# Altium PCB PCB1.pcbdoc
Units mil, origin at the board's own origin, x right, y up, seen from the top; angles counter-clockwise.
Board outline 2593.1 x 4516.05 mil, 2 copper layers (Top Layer, Bottom Layer); 41 components, 22 nets, 155 pads, 15 vias.
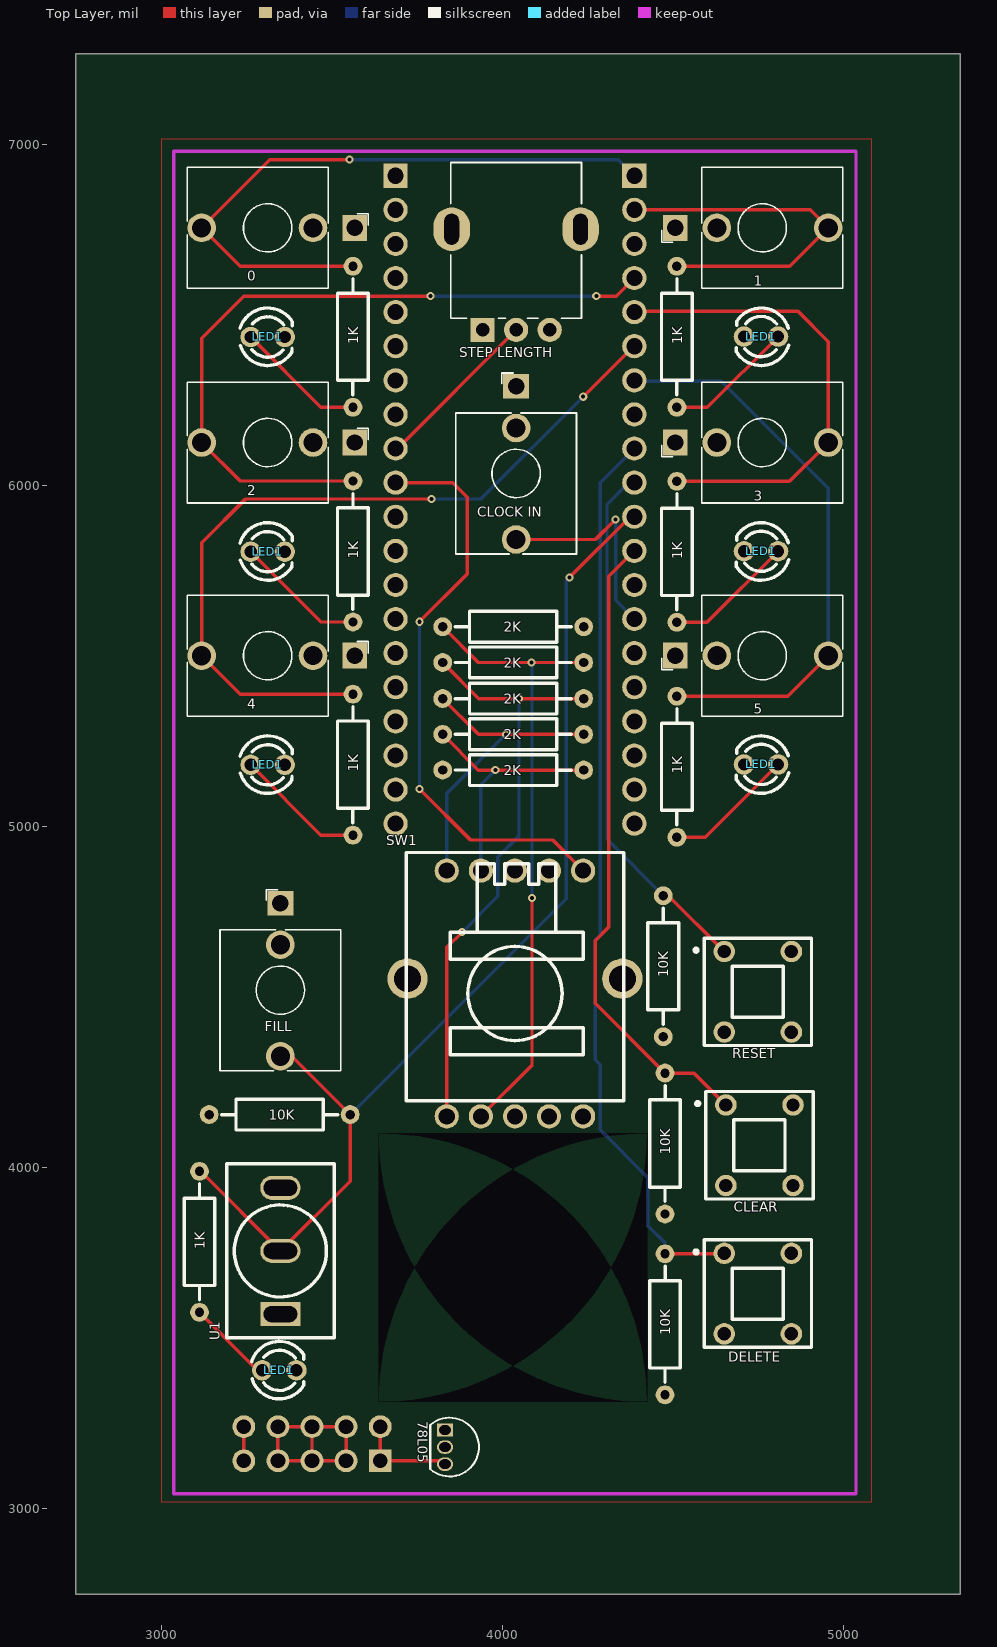
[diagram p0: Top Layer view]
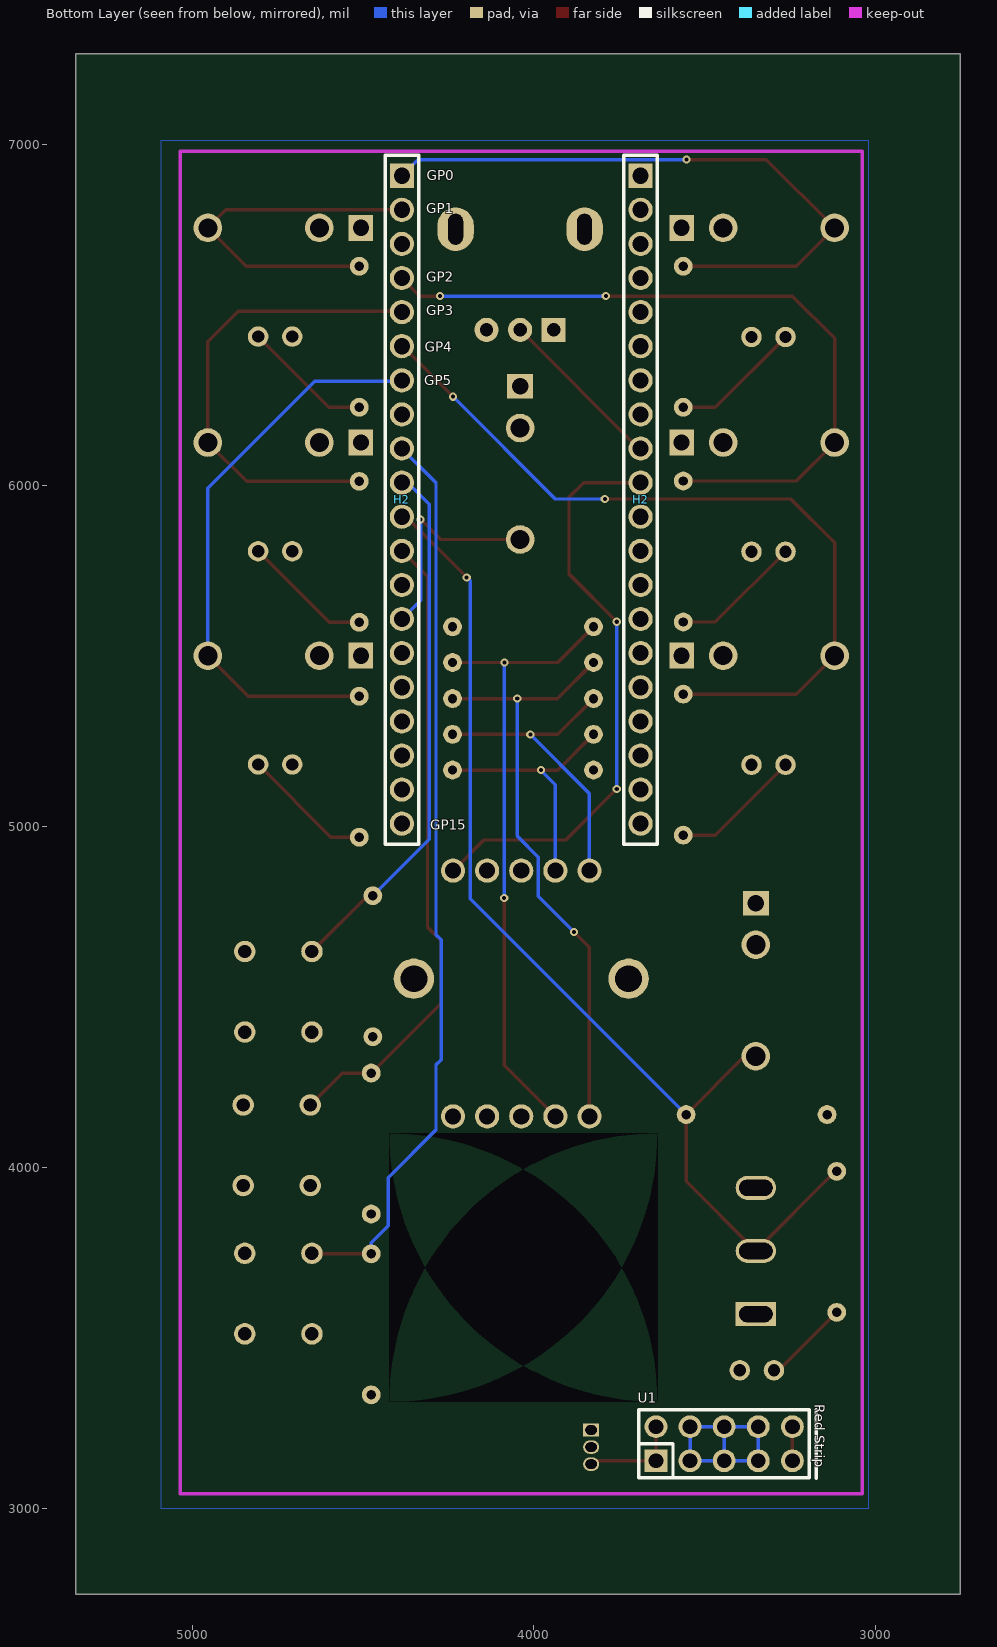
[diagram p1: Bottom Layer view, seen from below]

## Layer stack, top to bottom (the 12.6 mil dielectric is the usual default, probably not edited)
Top Layer: signal copper (thickness not stored)
Dielectric: dielectric 12.6, FR-4, Dk 4.8
Bottom Layer: signal copper (thickness not stored)

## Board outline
5343.1,2750 2750,2750 2750,7266.05 5343.1,7266.05
cut-out: 4424.72,4101.05 3637.32,4101.05 cw(c3637.32,3313.65) 4424.72,3313.65 4424.72,4101.05 cw(c3637.32,4101.05) 3637.32,3313.65 4424.72,3313.65 cw(c4424.72,4101.05) 3637.32,4101.05 3637.32,3313.65 cw(c4424.72,3313.65)

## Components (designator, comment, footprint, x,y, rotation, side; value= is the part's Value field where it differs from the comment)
0 "Connector_AudioJack2_SwitchT" benjiaomodular:AudioJack_3.5mm 3567.32,6756.05 r270 top
1 "Connector_AudioJack2_SwitchT" benjiaomodular:AudioJack_3.5mm 4507.31,6756.05 r90 top
1K "MF1/4W-1KΩ±1%T52" RES-TH_BD2.3-L6.5-P10.50-D0.5 3562.32,6436.64 r90 top
1K "MF1/4W-1KΩ±1%T52" RES-TH_BD2.3-L6.5-P10.50-D0.5 4512.31,6436.64 r90 top
1K "MF1/4W-1KΩ±1%T52" RES-TH_BD2.3-L6.5-P10.50-D0.5 3562.32,5807.13 r90 top
1K "MF1/4W-1KΩ±1%T52" RES-TH_BD2.3-L6.5-P10.50-D0.5 4512.31,5806.05 r90 top
1K "MF1/4W-1KΩ±1%T52" RES-TH_BD2.3-L6.5-P10.50-D0.5 3562.32,5182.13 r90 top
1K "MF1/4W-1KΩ±1%T52" RES-TH_BD2.3-L6.5-P10.50-D0.5 4512.31,5176.05 r90 top
1K "MF1/4W-1KΩ±1%T52" RES-TH_BD2.3-L6.5-P10.50-D0.5 3112.32,3782.71 r90 top
2 "Connector_AudioJack2_SwitchT" benjiaomodular:AudioJack_3.5mm 3567.32,6126.54 r270 top
2K "MF1/4W-1KΩ±1%T52" RES-TH_BD2.3-L6.5-P10.50-D0.5 4032.1,5375.84 r0 top
2K "MF1/4W-1KΩ±1%T52" RES-TH_BD2.3-L6.5-P10.50-D0.5 4032.1,5270.84 r0 top
2K "MF1/4W-1KΩ±1%T52" RES-TH_BD2.3-L6.5-P10.50-D0.5 4032.1,5166.26 r0 top
2K "MF1/4W-1KΩ±1%T52" RES-TH_BD2.3-L6.5-P10.50-D0.5 4032.1,5481.66 r0 top
2K "MF1/4W-1KΩ±1%T52" RES-TH_BD2.3-L6.5-P10.50-D0.5 4032.1,5586.23 r0 top
3 "Connector_AudioJack2_SwitchT" benjiaomodular:AudioJack_3.5mm 4507.31,6126.54 r90 top
4 "Connector_AudioJack2_SwitchT" benjiaomodular:AudioJack_3.5mm 3567.32,5501.54 r270 top
5 "Connector_AudioJack2_SwitchT" benjiaomodular:AudioJack_3.5mm 4507.31,5501.54 r90 top
10K "MF1/4W-1KΩ±1%T52" RES-TH_BD2.3-L6.5-P10.50-D0.5 3347.32,4156.05 r0 top
10K "MF1/4W-1KΩ±1%T52" RES-TH_BD2.3-L6.5-P10.50-D0.5 4472.31,4591.05 r90 top
10K "MF1/4W-1KΩ±1%T52" RES-TH_BD2.3-L6.5-P10.50-D0.5 4477.31,4071.05 r90 top
10K "MF1/4W-1KΩ±1%T52" RES-TH_BD2.3-L6.5-P10.50-D0.5 4477.31,3540.8 r90 top
78L05 "BC558" TO-92-3_L4.5-W3.5-P1.27-L 3832.32,3181.05 r270 top
CLEAR "BTSA-N-P-17" SW-TH_BTSA-X-P-17 4754.27,4066.05 r0 top
"CLOCK IN" "Connector_AudioJack2_SwitchT" benjiaomodular:AudioJack_3.5mm 4040.74,6291.05 r0 top
DELETE "BTSA-N-P-17" SW-TH_BTSA-X-P-17 4749.47,3631.05 r0 top
FILL "Connector_AudioJack2_SwitchT" benjiaomodular:AudioJack_3.5mm 3349.56,4776.05 r0 top
H2 "22850120ANG1SYA01" HDR-TH_20P-P2.54-V-F 4387.31,5958.97 r270 bottom
H2 "22850120ANG1SYA01" HDR-TH_20P-P2.54-V-F 3687.31,5958.97 r270 bottom
LED1 "204-10SURD/S530-A3-L" LED-TH_BD3.0-P2.54-FD 3312.32,6436.05 r0 top
LED1 "204-10SURD/S530-A3-L" LED-TH_BD3.0-P2.54-FD 4758.8,6437.23 r180 top
LED1 "204-10SURD/S530-A3-L" LED-TH_BD3.0-P2.54-FD 4758.8,5807.72 r180 top
LED1 "204-10SURD/S530-A3-L" LED-TH_BD3.0-P2.54-FD 3312.32,5806.54 r0 top
LED1 "204-10SURD/S530-A3-L" LED-TH_BD3.0-P2.54-FD 4758.8,5182.72 r180 top
LED1 "204-10SURD/S530-A3-L" LED-TH_BD3.0-P2.54-FD 3312.32,5181.54 r0 top
LED1 "204-10SURD/S530-A3-L" LED-TH_BD3.0-P2.54-FD 3346.43,3406.05 r0 top
RESET "BTSA-N-P-17" SW-TH_BTSA-X-P-17 4749.47,4516.05 r0 top
"STEP LENGTH" "BusinessCardOscillator-rescue_R_POT-Device" benjiaomodular:Potentiometer_RV09 3942.32,6456.84 r90 top
SW1 "SRBV151102" SW-TH_SRBV151102 4037.32,4511.05 r0 top
U1 "MT-0-102-A101-M200-RS" SW-TH_MT-0-103-A101-M200-RS 3349.56,3756.05 r90 top
U1 "ZX-PZ2.54-2-5PZZ" HDR-TH_10P-P2.54-V-M-R2-C5-S2.54 3442.32,3190.83 r180 bottom

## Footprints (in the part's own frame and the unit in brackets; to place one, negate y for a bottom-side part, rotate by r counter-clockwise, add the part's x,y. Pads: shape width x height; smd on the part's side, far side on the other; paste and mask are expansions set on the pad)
benjiaomodular:AudioJack_3.5mm [mm]
  rect 1.93x1.83 hole 1.22: S(0,0)
  round 2.13 hole 1.43: T(0,-11.4)
  round 2.13 hole 1.42: TN(0,-3.1)
  silkscreen extent -4.5,-12.48 4.5,1
benjiaomodular:Potentiometer_RV09 [mm]
  rect 1.8x1.8 hole 1: 1(0,0)
  round 1.8 hole 1: 2(0,-2.5) 3(0,-5)
  oval 3.24x2.72 hole 1.1 slot 2.3 at 0 deg: 4(7.5,-7.3) 5(7.5,2.3)
  silkscreen extent 0.88,-7.37 12.47,2.38
HDR-TH_10P-P2.54-V-M-R2-C5-S2.54 [mm]
  rect 1.7x1.7 hole 1.1: 1(-5.08,-1.27)
  round 1.7 hole 1.1: 2(-5.08,1.27) 3(-2.54,-1.27) 4(-2.54,1.27) 5(0,-1.27) 6(0,1.27) 7(2.54,-1.27) 8(2.54,1.27) 9(5.08,-1.27) 10(5.08,1.27)
  silkscreen extent -6.35,-2.54 6.35,2.54
HDR-TH_20P-P2.54-V-F [mm]
  rect 1.8x1.8 hole 1.2: 1(-24.13,0)
  round 1.8 hole 1.2: 2(-21.59,0) 3(-19.05,0) 4(-16.51,0) 5(-13.97,0) 6(-11.43,0) 7(-8.89,0) 8(-6.35,0) 9(-3.81,0) 10(-1.27,0) 11(1.27,0) 12(3.81,0) 13(6.35,0) 14(8.89,0) 15(11.43,0) 16(13.97,0) 17(16.51,0) 18(19.05,0) 19(21.59,0) 20(24.13,0)
  silkscreen extent -25.65,-1.25 25.65,1.25
LED-TH_BD3.0-P2.54-FD [mil]
  round 60 hole 36: 1(-50,0) 2(50,0)
  silkscreen extent -81,-84 72,85
RES-TH_BD2.3-L6.5-P10.50-D0.5 [mm]
  round 1.4 hole 0.7: 1(-5.25,0) 2(5.25,0)
  silkscreen extent -4.32,-1.15 4.32,1.15
SW-TH_BTSA-X-P-17 [mm]
  round 1.6 hole 1: 1(-2.5,3) 2(2.5,3) 3(-2.5,-3) 4(2.5,-3)
  silkscreen extent -4.74,-4 4,4
SW-TH_MT-0-103-A101-M200-RS [mm]
  rect 1.8x3 hole 1.2 slot 2.5 at 90 deg: 1(-4.7,0)
  oval 1.8x3 hole 1.2 slot 2.5 at 90 deg: 2(0,0) 3(4.7,0)
  silkscreen extent -6.48,-4 6.5,4
SW-TH_SRBV151102 [mm]
  round 1.8 hole 1.2: 1(5.08,-9.15) 2(2.54,-9.15) 3(0,-9.15) 4(-2.54,-9.15) 5(-5.08,-9.15) 6(-5.08,9.15) 7(-2.54,9.15) 8(0,9.15) 9(2.54,9.15) 10(5.08,9.15)
  round 3 hole 2: 11(8,1.1) 12(-8,1.1)
  silkscreen extent -8.1,-8 8.1,10.5
TO-92-3_L4.5-W3.5-P1.27-L [mm]
  rect 1x1.2 hole 0.7 slot 0.85 at 90 deg: 1(-1.27,0)
  oval 1x1.2 hole 0.7 slot 0.85 at 90 deg: 2(0,0) 3(1.27,0)
  silkscreen extent -2.19,-1.1 2.19,2.52

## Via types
v1: diameter 24.02, hole 12.01, Top Layer to Bottom Layer, 15 vias

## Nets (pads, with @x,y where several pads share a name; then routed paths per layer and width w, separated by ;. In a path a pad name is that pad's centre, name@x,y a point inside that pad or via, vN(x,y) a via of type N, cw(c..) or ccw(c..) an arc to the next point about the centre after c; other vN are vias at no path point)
4: 2K.1@3825.42,5586.23 2K.2@4238.79,5481.66 SW1.4 | length 1850.2
  Top Layer w10: 2K.1@3825.41,5586.23 3929.99,5481.66 v1(4085.97,5481.66) 2K.2@4238.79,5481.66 ; SW1.4 4087.32,4300.81 v1(4087.32,4791.05)
  Bottom Layer w10: v1(4085.97,5481.66) 4087.32,5480.31 v1(4087.32,4791.05)
5: 2K.1@3825.42,5481.66 2K.2@4238.79,5375.84 SW1.5 | length 1770
  Top Layer w10: 2K.1@3825.41,5481.66 3931.23,5375.84 v1(4049.11,5375.84) 2K.2@4238.79,5375.84 ; SW1.5 3837.32,4646.05 v1(3882.32,4691.05)
  Bottom Layer w10: v1(3882.32,4691.05) 3987.32,4796.05 3987.32,4911.05 4049.11,4972.84 v1(4049.11,5375.84)
6: 2K.1@3825.42,5375.84 2K.2@4238.79,5270.84 SW1.6 | length 928.3
  Top Layer w10: 2K.1@3825.41,5375.84 3930.41,5270.84 v1(4010.77,5270.84) 2K.2@4238.79,5270.84
  Bottom Layer w10: SW1.6 3837.32,5097.38 v1(4010.77,5270.84)
7: 2K.1@3825.42,5270.84 2K.2@4238.79,5166.26 SW1.7 | length 769.2
  Top Layer w10: 2K.1@3825.41,5270.84 3930.2,5166.05 v1(3979.81,5166.05) 4238.58,5166.05 2K.2@4238.79,5166.26
  Bottom Layer w10: SW1.7 3937.32,5123.56 v1(3979.81,5166.05)
+5: 2K.1@3825.42,5166.26 78L05.1 "STEP LENGTH.1" CLEAR.2 DELETE.2 RESET.2 SW1.8 U1.3@3349.56,3941.09
+12: 78L05.3 U1.1@3642.32,3140.83 U1.2@3642.32,3240.83 | length 294.1
  Top Layer w10: U1.2@3642.32,3240.83 3642.32,3140.83 3822.53,3140.83 78L05.3
-12: U1.9 U1.10 | length 100
  Top Layer w10: U1.9 U1.10
GND: 0.S 1.S 2.S 2K.2@4238.79,5586.23 3.S 4.S 5.S 10K.1 78L05.2 "CLOCK IN.S" "STEP LENGTH.3" FILL.S H2.3 H2.8 H2.13 H2.18 LED1.2 SW1.3 U1.3@3542.32,3140.83 U1.4 U1.5 U1.6 U1.7 U1.8 | length 1400
  Top Layer w10: U1.5 U1.6 ; U1.5 U1.7 U1.8 U1.6 ; U1.5 3542.32,3140.83 U1.4 U1.6
  Bottom Layer w10: U1.5 3542.32,3140.83 U1.4 U1.6 ; U1.5 U1.7 U1.8 U1.6 ; U1.5 U1.6
GP0: 0.T 1K.2@3562.31,6643.33 H2.1@4387.31,6908.97 | length 1861.7
  Top Layer w10: v1(3552.32,6956.05) 3318.5,6956.05 0.T 3231.21,6643.33 1K.2@3562.32,6643.33
  Bottom Layer w10: v1(3552.32,6956.05) 4340.24,6956.05 H2.1@4387.31,6908.97
GP1: 1.T 1K.2@4512.31,6643.33 H2.2@4387.31,6808.97 | length 1081.2
  Top Layer w10: H2.2@4387.31,6808.97 4903.21,6808.97 1.T 4843.42,6643.33 1K.2@4512.31,6643.33
GP2: 1K.2@3562.31,6013.82 2.T H2.4@4387.31,6608.97 | length 2138.2
  Top Layer w10: 1K.2@3562.32,6013.82 3231.21,6013.82 2.T 3118.5,6432.23 3242.32,6556.05 v1(3789.39,6556.05) ; v1(4275.98,6556.05) 4334.39,6556.05 H2.4@4387.31,6608.97
  Bottom Layer w10: v1(3789.39,6556.05) v1(4275.98,6556.05)
GP3: 1K.2@4512.31,6012.74 3.T H2.5@4387.31,6508.97 | length 1393.1
  Top Layer w10: H2.5@4387.31,6508.97 4389.39,6511.05 4867.31,6511.05 4956.13,6422.23 3.T 4842.33,6012.74 1K.2@4512.31,6012.74
GP4: 1K.2@3562.31,5388.82 4.T H2.6@4387.31,6408.97 | length 2328.9
  Top Layer w10: 1K.2@3562.32,5388.82 3231.21,5388.82 4.T 3118.5,5832.23 3247.32,5961.05 v1(3792.32,5961.05) ; v1(4237.31,6261.05) 4385.24,6408.97 H2.6@4387.31,6408.97
  Bottom Layer w10: v1(3792.32,5961.05) 3937.32,5961.05 v1(4237.31,6261.05)
GP5: 1K.2@4512.31,5382.74 5.T H2.7@4387.31,6308.97 | length 1683.7
  Top Layer w10: 1K.2@4512.31,5382.74 4837.33,5382.74 5.T
  Bottom Layer w10: H2.7@4387.31,6308.97 4390.24,6306.05 4642.31,6306.05 4956.13,5992.23 5.T
GP6: 10K.2@4477.31,3747.49 DELETE.1 H2.9@4387.31,6108.97 | length 2668.5
  Top Layer w10: 10K.2@4477.31,3747.49 4649.38,3747.49 DELETE.1
  Bottom Layer w10: H2.9@4387.31,6108.97 4287.31,6008.97 4287.31,4683.37 4272.31,4668.37 4272.31,4316.82 4287.31,4301.82 4287.31,4111.05 4427.31,3971.05 4427.31,3830.05 4477.31,3780.05 10K.2@4477.31,3747.49
GP7: 10K.2@4472.31,4797.74 H2.10@4387.31,6008.97 RESET.1 | length 1569.2
  Top Layer w10: 10K.2@4472.31,4797.74 4487.47,4797.74 RESET.1
  Bottom Layer w10: H2.10@4387.31,6008.97 4370.24,6008.97 4307.31,5946.05 4307.31,4962.74 10K.2@4472.31,4797.74
GP8: 1K.2@3112.31,3989.4 10K.2@3554,4156.05 FILL.T H2.11@4387.31,5908.97 U1.2@3349.56,3756.05 | length 3199.1
  Top Layer w10: 1K.2@3112.32,3989.4 3116.21,3989.4 3349.56,3756.05 3554.01,3960.5 3554.01,4156.05 3382.82,4327.23 FILL.T ; v1(4197.31,5731.05) 4375.24,5908.97 H2.11@4387.31,5908.97
  Bottom Layer w10: 10K.2@3554.01,4156.05 4187.31,4789.36 4187.31,5721.05 v1(4197.31,5731.05)
GP9: 10K.2@4477.31,4277.74 CLEAR.1 H2.12@4387.31,5808.97 | length 1881.1
  Top Layer w10: H2.12@4387.31,5808.97 4312.31,5733.97 4312.31,4706.05 4272.31,4666.05 4272.31,4482.74 4477.31,4277.74 4562.26,4277.74 CLEAR.1
GP10: "CLOCK IN.T" H2.14@4387.31,5608.97 | length 630.8
  Top Layer w10: 4040.74,5842.23 4273.5,5842.23 v1(4332.31,5901.05)
  Bottom Layer w10: v1(4332.31,5901.05) 4332.31,5663.97 H2.14@4387.31,5608.97
GP26: H2.10@3687.31,6008.97 SW1.10 | length 1720.3
  Top Layer w10: H2.10@3687.31,6008.97 3854.39,6008.97 3897.32,5966.05 3897.32,5741.05 v1(3757.32,5601.05) ; v1(3757.32,5110.74) 3907.01,4961.05 4147.55,4961.05 SW1.10
  Bottom Layer w10: v1(3757.32,5110.74) v1(3757.32,5601.05)
GP27: "STEP LENGTH.2" H2.9@3687.31,6108.97 | length 497.5
  Top Layer w10: H2.9@3687.31,6108.97 3692.87,6108.97 4040.74,6456.84
"": 0.TN 1.TN 1K.1 2.TN 3.TN 4.TN 5.TN "CLOCK IN.TN" "STEP LENGTH.4" "STEP LENGTH.5" CLEAR.3 CLEAR.4 DELETE.3 DELETE.4 FILL.TN H2.1@3687.31,6908.97 H2.2@3687.31,6808.97 H2.4@3687.31,6608.97 H2.5@3687.31,6508.97 H2.6@3687.31,6408.97 H2.7@3687.31,6308.97 H2.11@3687.31,5908.97 H2.12@3687.31,5808.97 H2.14@3687.31,5608.97 H2.15 H2.16 H2.17 H2.19 H2.20 LED1.1 RESET.3 RESET.4 SW1.1 SW1.2 SW1.9 SW1.11 SW1.12 U1.1@3349.56,3571.01 | length 2560.6
  Top Layer w10: 1K.1@3112.32,3576.02 3282.28,3406.05 LED1.1@3296.43,3406.05 ; LED1.1@3262.32,5181.54 3468.41,4975.44 1K.1@3562.32,4975.44 ; LED1.1@3262.32,5806.54 3468.41,5600.44 1K.1@3562.32,5600.44 ; LED1.1@3262.32,6436.05 3468.41,6229.95 1K.1@3562.32,6229.95 ; 1K.1@4512.31,4969.36 4595.44,4969.36 LED1.1@4808.8,5182.72 ; 1K.1@4512.31,5599.36 4600.44,5599.36 LED1.1@4808.8,5807.72 ; 1K.1@4512.31,6229.95 4601.52,6229.95 LED1.1@4808.8,6437.23

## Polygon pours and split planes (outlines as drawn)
GND on Top Layer (solid, remove dead copper, pour order 0): 3000,3020.73 5083.1,3020.73 5083.1,7016.05 3000,7016.05
+5 on Bottom Layer (solid, remove dead copper, pour order 1): 3019.62,3000 5093.1,3000 5093.1,7013.01 3019.62,7013.01

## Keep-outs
Board Outline Layer:
  lines w10 net "": 3037.32,3044.04 5037.31,3044.04 5037.31,6981.05 3037.32,6981.05 3037.32,3044.04

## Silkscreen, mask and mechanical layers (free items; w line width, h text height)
Bottom Silkscreen Layer:
  lines w10 net "": 3172.32,3090.16 3172.32,3291.05
  text "GP0" at 4314.82,6896.04 h29.2
  text "GP1" at 4315.87,6798.54 h29.2
  text "GP2" at 4315.35,6597.29 h29.2
  text "GP3" at 4316.4,6499.79 h29.2
  text "GP4" at 4320.35,6392.29 h29.2
  text "GP5" at 4321.4,6294.79 h29.2
  text "GP15" at 4303.54,4991.04 h29.2
  text "Red Strip" at 3177.1,3306.03 h28.62 r90
Mechanical Layer:
  lines w1 net "": 3637.32,3313.65 ccw(c3637.32,4101.05) 4424.72,4101.05 ; 3637.32,3313.65 4424.72,3313.65 ; 3637.32,3313.65 3637.32,4101.05 ; 3637.31,3313.65 cw(c4424.72,3313.65) 4424.72,4101.05 ; 3637.32,4101.05 4424.72,4101.05 ; 3637.32,4101.05 cw(c3637.32,3313.65) 4424.72,3313.65 ; 3637.31,4101.05 ccw(c4424.72,4101.05) 4424.72,3313.65 ; 4424.72,3313.65 4424.72,4101.05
